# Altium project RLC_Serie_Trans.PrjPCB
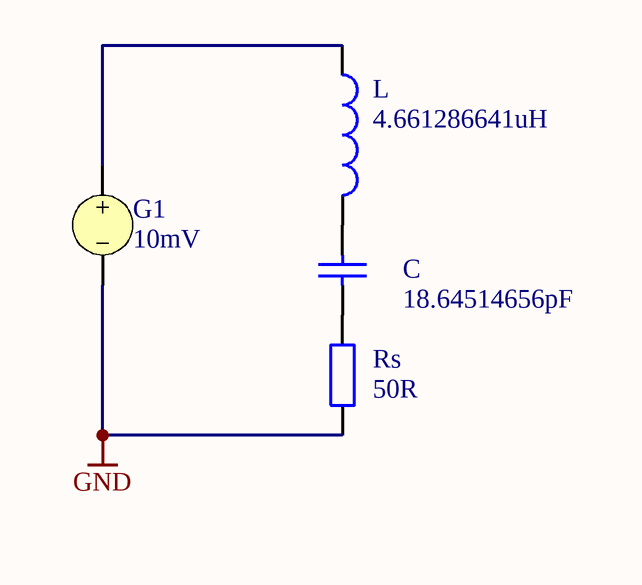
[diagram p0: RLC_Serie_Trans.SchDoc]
1 sheet, 4 parts. Net scope: global (net labels, ports and power ports of the same name join across sheets).

## Sheet RLC_Serie_Trans.SchDoc
size A4

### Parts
C  value 18.64514656pF  [RAD-0.3]  (hidden comment: Cap)
G1  value 10mV  (hidden comment: VSRC)
L  value 4.661286641uH  [0402-A]  (hidden comment: Inductor)
Rs  value 50R  [AXIAL-0.4]  (hidden comment: Res2)

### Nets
GND: G1.2 Rs.1
NetC_1: C.1 L.2
NetC_2: C.2 Rs.2
NetG1_1: G1.1 L.1

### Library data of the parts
C = Cap: Capacitor
G1 = VSRC: Voltage Source; Note: PCB Footprint - Not required
L = Inductor: Code_IEC: 1005
Rs = Res2: Resistor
